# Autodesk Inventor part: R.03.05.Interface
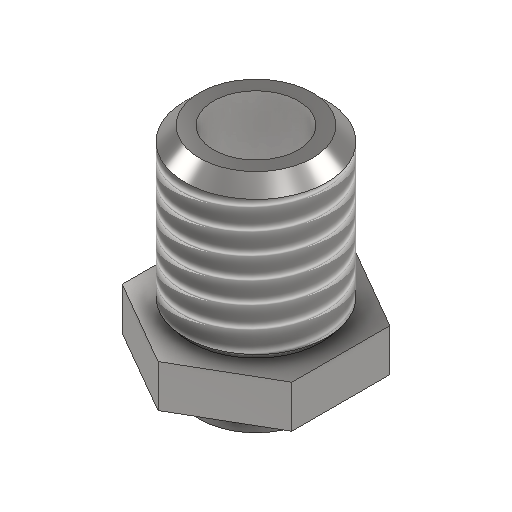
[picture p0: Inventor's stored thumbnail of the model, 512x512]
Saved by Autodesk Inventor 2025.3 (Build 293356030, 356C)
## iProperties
Created: 2021-02
Part Number: R.03.05.Interface
Material: Stainless Steel
Document SubType Name: Modeling
Designer: Михальчик
Density: 8 g/cm^3
Appearance: Semi-Polished
Author: Михальчик
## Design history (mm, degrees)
sketch "Sketch1"
  geometry: L1 (0, 0)-(0, 26.913); L2 (0, 0)-(4, 0); L3 (4, 0)-(4, 2); L4 (4, 2)-(0, 2); L5 (0, 2)-(0, 0); L6 (0, 2)-(7, 2); L7 (7, 2)-(7, 5); L8 (7, 5)-(0, 5); L9 (0, 5)-(0, 2); L10 (0, 5)-(4.6, 5); L11 (4.6, 5)-(4.6, 5.5); L12 (4.6, 5.5)-(0, 5.5); L13 (0, 5.5)-(0, 5); L14 (0, 5.5)-(5, 5.5); L15 (5, 5.5)-(5, 16); L16 (5, 16)-(0, 16); L17 (0, 16)-(0, 5.5); L18 (0, 0)-(3, 0); L19 (3, 0)-(3, 16); L20 (3, 16)-(0, 16); L21 (0, 16)-(0, 0); L22 (5.4, 5)-(7, 5); L23 (5.4, 5)-(7, 5); L24 (7, 2)-(5.4, 2); 4 further points
  constraints: 48 end point, 10 parallel, 6 horizontal, 5 perpendicular, 5 point on line, 2 equal length, 1 vertical
  dimensions: "d0" = 4 distance of L4.end L3.end; "d1" = 2 distance of L3.end L2.end; "d2" = 7 distance of L8.end L7.end; "d3" = 3 distance of L7.end L6.end; "d4" = 4.6 distance of L12.end L11.end; "d5" = 16 distance between parallel lines of L2 L16; "d6" = 5 distance of L15.end L16.end; "d7" = 3 distance of L20.end L19.end; "d8" = 0.5 distance of L10.end L11.end; "d9" = 0 distance between parallel lines of L22 L23; "d10" = 0 distance between parallel lines of L6 L24; "d11" = 1.6 distance of L22.start L22.end
revolve "Revolution1" sketch "Sketch1" stored, may be unused: angle "d12" = 90 deg
chamfer "Chamfer1" distance "d13" = 1; stored, may be unused: second distance "d14" = 2, angle "d15" = 45 deg
thread "Thread1" dims "d16" = 8, "d17" = 0
sketch "Sketch2"
  geometry: L1 (0, -6.928)-(-6, -3.464); L2 (-6, -3.464)-(-6, 3.464); L3 (-6, 3.464)-(0, 6.928); L4 (0, 6.928)-(6, 3.464); L5 (6, 3.464)-(6, -3.464); L6 (6, -3.464)-(0, -6.928); C1 r 7 at (0, 0); C2 r 7 at (0, 0) reference; 2 further points
  constraints: 12 end point, 2 coincident, 1 centre point, 1 concentric, 1 vertical, 13 other
  dimensions: "d18" = 12 distance between parallel lines of L2 L5
extrude "Extrusion1" cut sketch "Sketch2" distance "d19" = 10; taper "d20" = 0 deg
fillet "Raccordo1" dims "d21" = 2
body "Solid1"
